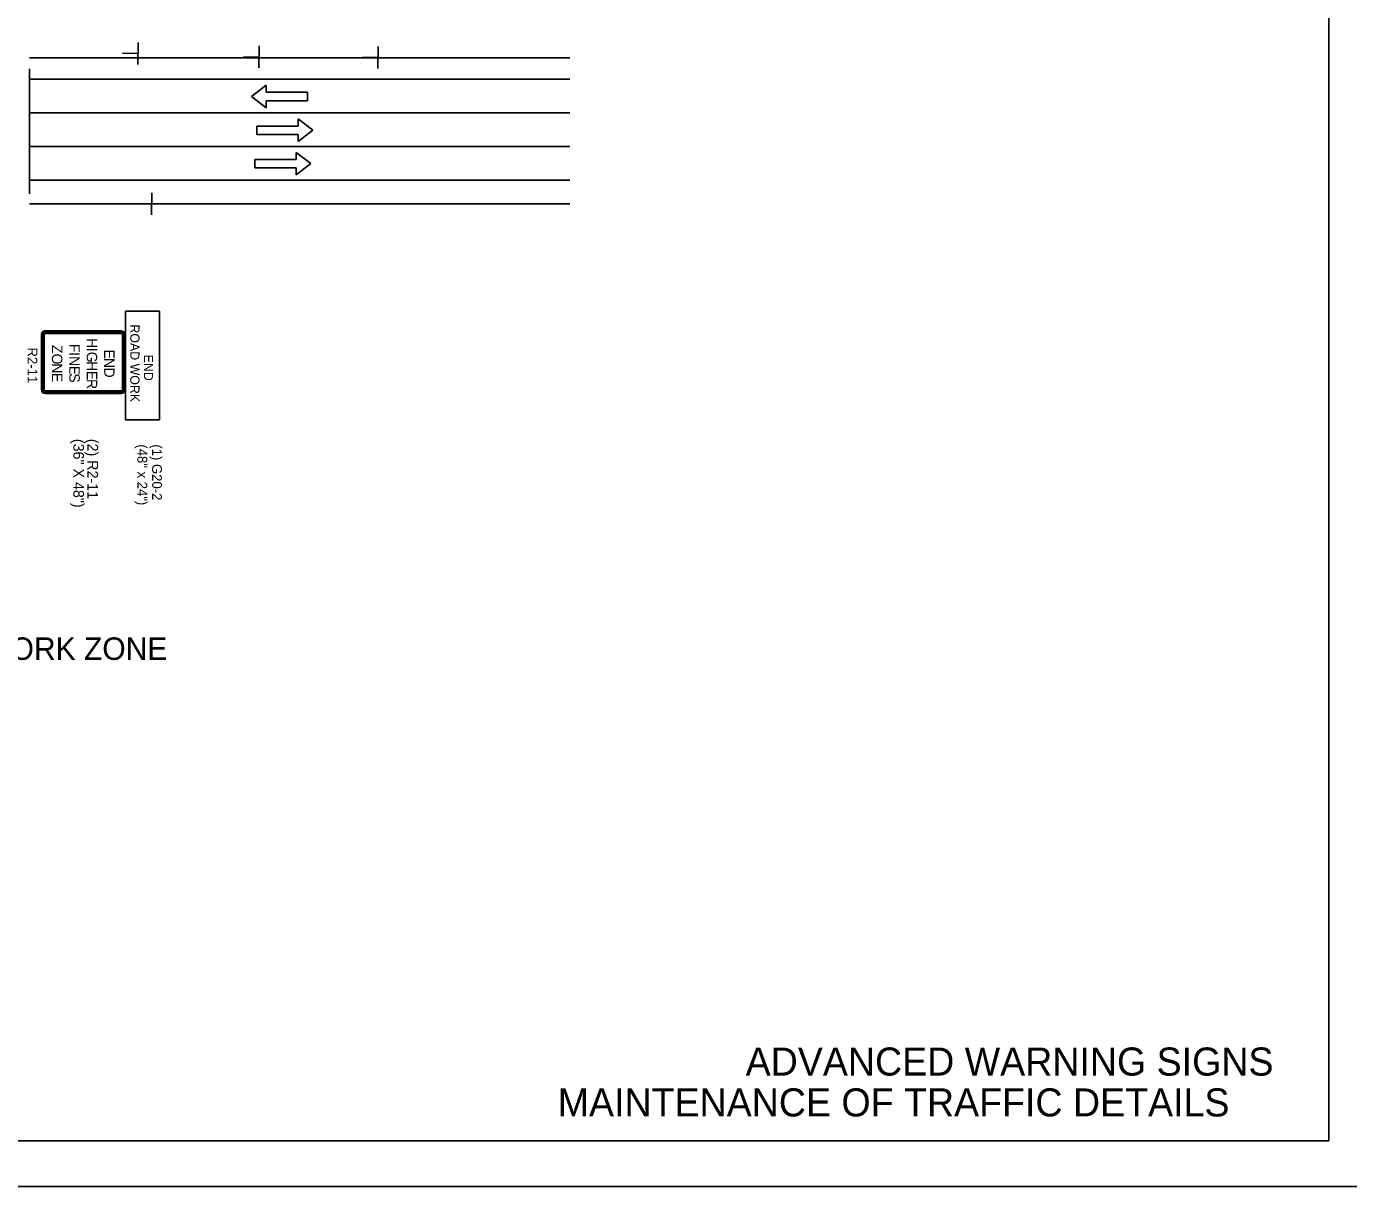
# Model space of a CAD drawing. Extents: x 32485 to 39285, y 55121 to 58033.
# Drawn here: x 36848 to 37571, y 56764 to 57398 of the extents above; entities that cross this region are included whole.
import ezdxf

# ---------------------------------------------------------------- set-up
doc = ezdxf.new("R2010")
doc.units = 0
for name, color, linetype in [('Default', 7, 'Continuous'), ('R_Border', 7, 'Continuous'), ('R_Border Notes', 7, 'Continuous'), ('R_Draft', 7, 'Continuous'), ('R_Exist Surface', 7, 'Continuous'), ('R_MOT', 7, 'Continuous')]:
    doc.layers.add(name, color=color, linetype=linetype)

msp = doc.modelspace()

# ---------------------------------------------------------------- linework, layer by layer
at = {"layer": 'Default'}
for p, q in [((36849.79, 57374.92), (36849.79, 57306.5)), ((36971.26, 57359.7), (36979.22, 57365.83)), ((36979.22, 57362), (36979.22, 57365.83)), ((36979.22, 57353.56), (36971.26, 57359.7)), ((36979.22, 57362), (37001.79, 57362)), ((36979.22, 57357.39), (37001.79, 57357.39)), ((36979.22, 57353.56), (36979.22, 57357.39)), ((37001.79, 57357.39), (37001.79, 57362)), ((36996.71, 57343.58), (36974.14, 57343.58)), ((36974.14, 57343.58), (36974.14, 57338.98)), ((36996.71, 57347.42), (36996.71, 57343.58)), ((36996.71, 57347.42), (37004.67, 57341.28)), ((37004.67, 57341.28), (36996.71, 57335.15)), ((36996.71, 57338.98), (36974.14, 57338.98)), ((36996.71, 57338.98), (36996.71, 57335.15)), ((36995.64, 57329.18), (36995.64, 57325.34)), ((36995.64, 57329.18), (37003.61, 57323.04)), ((36995.64, 57325.34), (36973.07, 57325.34)), ((36973.07, 57325.34), (36973.07, 57320.74)), ((36995.64, 57320.74), (36973.07, 57320.74)), ((37003.61, 57323.04), (36995.64, 57316.9)), ((36995.64, 57320.74), (36995.64, 57316.9)), ((36856.36, 57229.5), (36856.36, 57199.52)), ((36856.96, 57229.5), (36856.96, 57199.52)), ((36857.79, 57199.52), (36857.79, 57229.5)), ((36899.91, 57231.64), (36858.5, 57231.64)), ((36899.91, 57231.05), (36858.5, 57231.05)), ((36858.5, 57230.21), (36899.91, 57230.21)), ((36900.62, 57229.5), (36900.62, 57199.52)), ((36901.45, 57199.52), (36901.45, 57229.5)), ((36902.05, 57199.52), (36902.05, 57229.5)), ((36899.91, 57198.8), (36858.5, 57198.8)), ((36858.5, 57197.97), (36899.91, 57197.97)), ((36858.5, 57197.38), (36899.91, 57197.38))]:
    msp.add_line(p, q, dxfattribs=at)
msp.add_lwpolyline([(35885, 57863.91), (35885, 56763.91), (37585, 56763.91), (37585, 57863.91)], close=True, dxfattribs=at)
for centre, radius, start, end in [((36858.5, 57229.5), 2.14, 90, 180.00001), ((36858.5, 57229.5), 1.55, 90.00001, 180), ((36858.5, 57229.5), 0.714, 90.00001, 180), ((36899.91, 57229.5), 2.14, 0, 90), ((36899.91, 57229.5), 1.55, 0, 90.00001), ((36899.91, 57229.5), 0.714, 0, 90.00001), ((36858.5, 57199.52), 2.14, 180.00001, 270.00001), ((36858.5, 57199.52), 1.55, 180, 270.00001), ((36858.5, 57199.52), 0.714, 180, 270.00001), ((36899.91, 57199.52), 2.14, 270, 0), ((36899.91, 57199.52), 1.55, 270, 0), ((36899.91, 57199.52), 0.714, 270, 0)]:
    msp.add_arc(centre, radius, start, end, dxfattribs=at)
at = {"layer": 'R_Border'}
for p, q in [((36908.99, 57377.2), (36909.19, 57389.24)), ((36975.15, 57375.29), (36975.36, 57387.33)), ((37040.24, 57374.99), (37040.45, 57387.03)), ((36908.91, 57383.19), (36900.69, 57383.33)), ((36975.08, 57381.28), (36966.86, 57381.42)), ((37040.17, 57380.98), (37031.94, 57381.12)), ((36916.64, 57307.01), (36916.58, 57294.96)), ((36916.78, 57301.01), (36925.01, 57300.98)), ((36902.27, 57183.04), (36902.27, 57242.3)), ((36902.27, 57242.3), (36920.88, 57242.3)), ((36920.88, 57183.04), (36920.88, 57242.3)), ((36902.27, 57183.04), (36920.88, 57183.04))]:
    msp.add_line(p, q, dxfattribs=at)
at = {"layer": 'R_Border Notes'}
for points in [[(35885, 56763.91), (37585, 56763.91), (37585, 57863.91), (35885, 57863.91)], [(35910, 56788.91), (37560, 56788.91), (37560, 57838.91), (35910, 57838.91)]]:
    msp.add_lwpolyline(points, close=True, dxfattribs=at)
at = {"layer": 'R_Exist Surface'}
for p, q in [((36849.79, 57380.8), (37145.16, 57380.8)), ((36849.79, 57369.14), (37145.16, 57369.14)), ((36849.79, 57350.73), (37145.16, 57350.73)), ((36849.79, 57332.32), (37145.16, 57332.32)), ((36849.79, 57313.91), (37145.16, 57313.91)), ((36849.77, 57301.05), (37145.13, 57301.05))]:
    msp.add_line(p, q, dxfattribs=at)

# ---------------------------------------------------------------- texts
at = {"layer": 'Default'}
for s, height, p in [('H', 5.71, (36881.11, 57227.62)), ('R2-11', 5.384, (36848.74, 57222.56)), ('O', 5.71, (36862.07, 57219.19)), ('Z', 5.71, (36862.07, 57223.94)), ('F', 5.71, (36871.59, 57224.48)), ('I', 5.71, (36871.59, 57220.08)), ('G', 5.71, (36881.11, 57220.19)), ('I', 5.71, (36881.11, 57222.37)), ('E', 5.71, (36890.63, 57221.34)), ('N', 5.71, (36862.07, 57213.88)), ('N', 5.71, (36871.59, 57217.79)), ('E', 5.71, (36871.59, 57212.53)), ('H', 5.71, (36881.11, 57215.05)), ('N', 5.71, (36890.63, 57216.82)), ('D', 5.71, (36890.63, 57211.56)), ('E', 5.71, (36862.07, 57208.62)), ('S', 5.71, (36871.59, 57208.42)), ('E', 5.71, (36881.11, 57209.79)), ('R', 5.71, (36881.11, 57205.28))]:
    msp.add_text(s, height=height, rotation=270, dxfattribs=at).set_placement(p)
msp.add_text('ADVANCE WARNING SIGNS AT BEGINNING AND END OF WORK ZONE ', height=12.2732, dxfattribs=at).set_placement((36372.6, 57051.78))
at = {"layer": 'R_Border'}
for s, height, p in [('ROAD WORK', 5.058, (36904.89, 57235.13)), ('END', 5.058, (36912.36, 57218.62)), ('(48" x 24")', 5.3523, (36908.82, 57169.59)), ('(1) G20-2', 5.353, (36916.85, 57169.59))]:
    msp.add_text(s, height=height, rotation=270, dxfattribs=at).set_placement(p)
at = {"layer": 'R_Draft'}
for s, height, p in [('(36" X 48")', 5.8301, (36873.76, 57172.58)), ('(2) R2-11', 5.83, (36881.49, 57172.58))]:
    msp.add_text(s, height=height, rotation=270, dxfattribs=at).set_placement(p)
at = {"layer": 'R_MOT'}
for s, p in [('ADVANCED WARNING SIGNS', (37241.3, 56824.56)), ('MAINTENANCE OF TRAFFIC DETAILS', (37138.57, 56802.23))]:
    msp.add_text(s, height=15.349, dxfattribs=at).set_placement(p)

doc.saveas('drawing.dxf')
